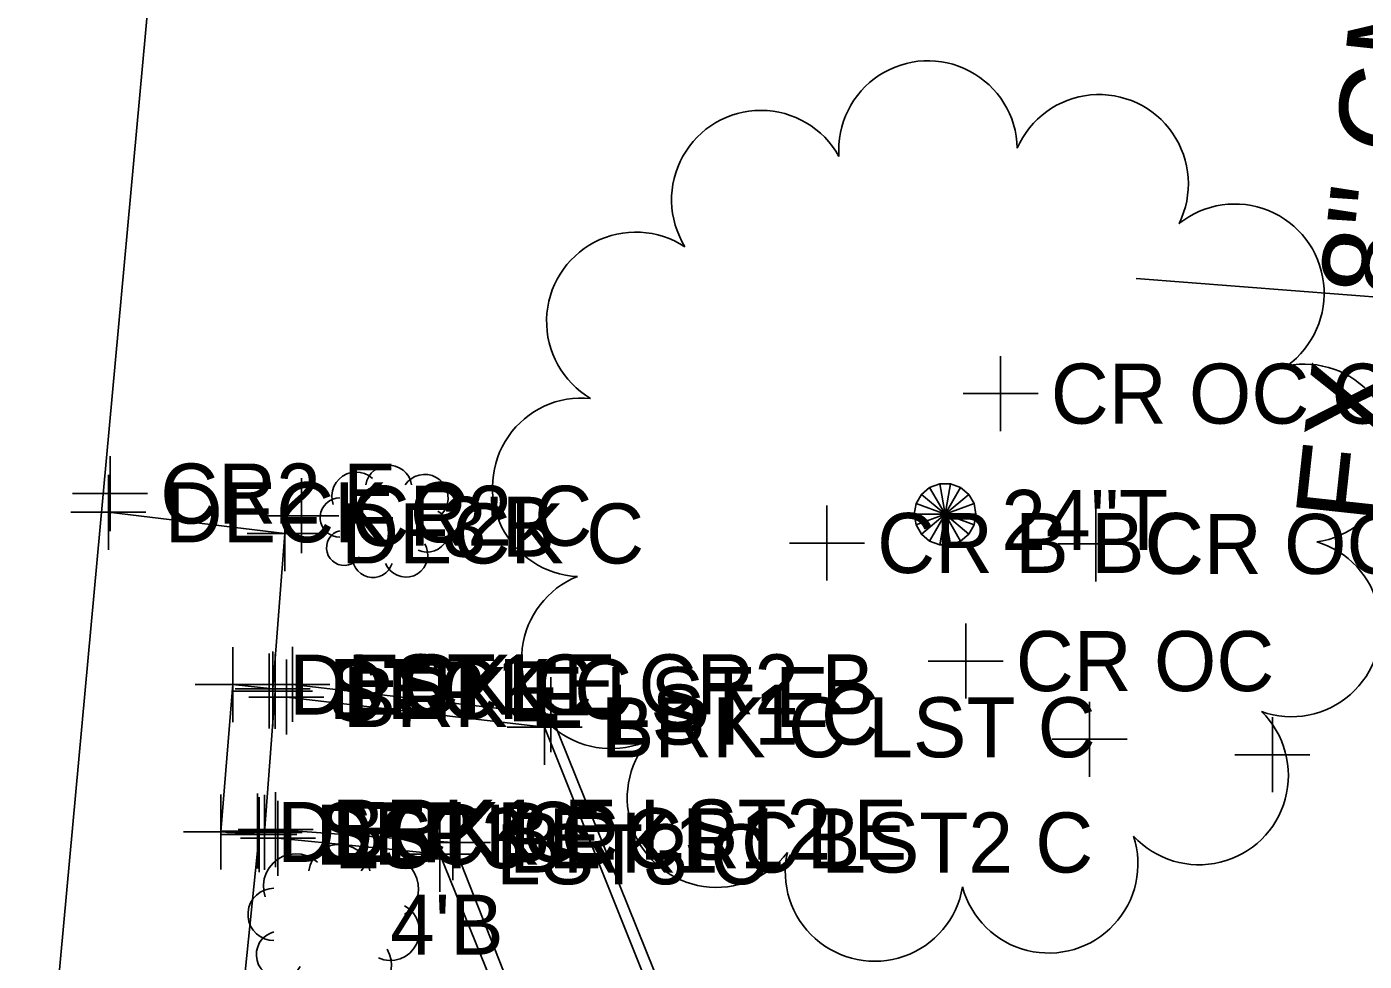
# Model space of a CAD drawing. Extents: x 1363693 to 1365209, y 422201 to 424153.
# Drawn here: x 1364202.37 to 1364238.05, y 423360.62 to 423385.53 of the extents above; entities that cross this region are included whole.
import ezdxf

# ---------------------------------------------------------------- set-up
doc = ezdxf.new("R2010")
doc.units = 0
for name, color, linetype in [('BD_X_Building', 7, 'Continuous'), ('PV_X_Driveway', 7, 'Continuous'), ('RD_X_Misc_Items', 7, 'Continuous'), ('SV_X_Original_Ground', 7, 'Continuous'), ('SV_X_Random_Point', 7, 'Continuous'), ('SV_X_Shot_Marker', 7, 'Continuous'), ('UT_X_Gas_Text', 7, 'Continuous'), ('UT_X_Sanitary_Line', 7, 'Continuous'), ('VG_X_Cells', 7, 'Continuous'), ('VG_X_Flower_Bed', 7, 'Continuous'), ('VG_X_Text', 7, 'Continuous')]:
    doc.layers.add(name, color=color, linetype=linetype)

msp = doc.modelspace()

# ---------------------------------------------------------------- linework, layer by layer
at = {"layer": 'BD_X_Building'}
msp.add_line((1364202.373, 423350.942), (1364205.953, 423389.813), dxfattribs=at)
at = {"layer": 'PV_X_Driveway'}
msp.add_line((1364208.715, 423364.055), (1364208.996, 423367.815), dxfattribs=at)
at = {"layer": 'RD_X_Misc_Items'}
for p, q in [((1364209.254, 423372.021), (1364204.553, 423372.586)), ((1364208.932, 423367.878), (1364209.254, 423372.021)), ((1364207.551, 423364.067), (1364207.868, 423367.994)), ((1364207.868, 423367.994), (1364208.932, 423367.878)), ((1364208.573, 423363.995), (1364207.551, 423364.067)), ((1364208.041, 423358.764), (1364208.573, 423363.995))]:
    msp.add_line(p, q, dxfattribs=at)
at = {"layer": 'SV_X_Original_Ground'}
for p, q in [((1364228.348, 423374.748), (1364228.348, 423376.748)), ((1364227.348, 423375.748), (1364229.348, 423375.748)), ((1364204.597, 423372.085), (1364204.597, 423374.085)), ((1364204.553, 423371.586), (1364204.553, 423373.586)), ((1364209.698, 423371.493), (1364209.698, 423373.493)), ((1364203.597, 423373.085), (1364205.597, 423373.085)), ((1364209.254, 423371.021), (1364209.254, 423373.021)), ((1364203.553, 423372.586), (1364205.553, 423372.586)), ((1364208.698, 423372.493), (1364210.698, 423372.493)), ((1364223.715, 423370.767), (1364223.715, 423372.767)), ((1364230.885, 423370.742), (1364230.885, 423372.742)), ((1364208.254, 423372.021), (1364210.254, 423372.021)), ((1364222.715, 423371.767), (1364224.715, 423371.767)), ((1364229.885, 423371.742), (1364231.885, 423371.742)), ((1364227.415, 423367.619), (1364227.415, 423369.619)), ((1364207.868, 423366.994), (1364207.868, 423368.994)), ((1364208.837, 423366.822), (1364208.837, 423368.822)), ((1364208.932, 423366.878), (1364208.932, 423368.878)), ((1364226.415, 423368.619), (1364228.415, 423368.619)), ((1364206.868, 423367.994), (1364208.868, 423367.994)), ((1364207.932, 423367.878), (1364209.932, 423367.878)), ((1364207.837, 423367.822), (1364209.837, 423367.822)), ((1364230.721, 423365.536), (1364230.721, 423367.536)), ((1364235.594, 423365.123), (1364235.594, 423367.123)), ((1364229.721, 423366.536), (1364231.721, 423366.536)), ((1364234.594, 423366.123), (1364236.594, 423366.123)), ((1364207.551, 423363.067), (1364207.551, 423365.067)), ((1364208.531, 423363.088), (1364208.531, 423365.088)), ((1364208.573, 423362.995), (1364208.573, 423364.995)), ((1364206.551, 423364.067), (1364208.551, 423364.067)), ((1364207.531, 423364.088), (1364209.531, 423364.088)), ((1364207.573, 423363.995), (1364209.573, 423363.995))]:
    msp.add_line(p, q, dxfattribs=at)
at = {"layer": 'SV_X_Random_Point'}
for p, q in [((1364209.459, 423366.999), (1364209.459, 423368.999)), ((1364208.996, 423366.815), (1364208.996, 423368.815)), ((1364208.459, 423367.999), (1364210.459, 423367.999)), ((1364216.348, 423366.193), (1364216.348, 423368.193)), ((1364207.996, 423367.815), (1364209.996, 423367.815)), ((1364215.348, 423367.193), (1364217.348, 423367.193)), ((1364208.715, 423363.055), (1364208.715, 423365.055)), ((1364209.074, 423362.896), (1364209.074, 423364.896)), ((1364213.391, 423362.471), (1364213.391, 423364.471)), ((1364207.715, 423364.055), (1364209.715, 423364.055)), ((1364208.074, 423363.896), (1364210.074, 423363.896)), ((1364212.391, 423363.471), (1364214.391, 423363.471))]:
    msp.add_line(p, q, dxfattribs=at)
at = {"layer": 'SV_X_Shot_Marker'}
for p, q in [((1364209.3, 423366.661), (1364209.3, 423368.661)), ((1364216.183, 423365.855), (1364216.183, 423367.855)), ((1364208.3, 423367.661), (1364210.3, 423367.661)), ((1364215.183, 423366.855), (1364217.183, 423366.855)), ((1364209.009, 423363.129), (1364209.009, 423365.129)), ((1364213.739, 423362.784), (1364213.739, 423364.784)), ((1364208.009, 423364.129), (1364210.009, 423364.129)), ((1364212.739, 423363.784), (1364214.739, 423363.784))]:
    msp.add_line(p, q, dxfattribs=at)
at = {"layer": 'UT_X_Sanitary_Line'}
msp.add_line((1364231.966, 423378.813), (1364264.406, 423376.309), dxfattribs=at)
at = {"layer": 'VG_X_Cells'}
for points in [[(1364211.592, 423373.489), (1364211.494, 423373.563), (1364211.384, 423373.617), (1364211.266, 423373.649), (1364211.144, 423373.658), (1364211.022, 423373.644), (1364210.906, 423373.607), (1364210.798, 423373.549), (1364210.703, 423373.472), (1364210.624, 423373.378), (1364210.564, 423373.271), (1364210.526, 423373.155), (1364210.51, 423373.034), (1364210.517, 423372.911), (1364210.547, 423372.793)], [(1364212.637, 423373.315), (1364212.61, 423373.429), (1364212.561, 423373.536), (1364212.493, 423373.631), (1364212.409, 423373.712), (1364212.31, 423373.775), (1364212.201, 423373.819), (1364212.086, 423373.841), (1364211.969, 423373.841), (1364211.854, 423373.819), (1364211.745, 423373.775), (1364211.647, 423373.712), (1364211.562, 423373.631), (1364211.494, 423373.536), (1364211.446, 423373.429), (1364211.418, 423373.315)], [(1364213.334, 423372.445), (1364213.425, 423372.518), (1364213.5, 423372.607), (1364213.558, 423372.708), (1364213.596, 423372.819), (1364213.613, 423372.934), (1364213.608, 423373.051), (1364213.582, 423373.165), (1364213.535, 423373.271), (1364213.469, 423373.368), (1364213.386, 423373.45), (1364213.29, 423373.516), (1364213.183, 423373.563), (1364213.069, 423373.589), (1364212.953, 423373.594), (1364212.837, 423373.577), (1364212.727, 423373.539), (1364212.626, 423373.481), (1364212.537, 423373.406), (1364212.463, 423373.315)], [(1364210.722, 423372.967), (1364210.625, 423372.958), (1364210.533, 423372.932), (1364210.446, 423372.889), (1364210.37, 423372.831), (1364210.305, 423372.759), (1364210.254, 423372.677), (1364210.219, 423372.587), (1364210.201, 423372.493), (1364210.201, 423372.396), (1364210.219, 423372.302), (1364210.254, 423372.212), (1364210.305, 423372.13), (1364210.37, 423372.058), (1364210.446, 423372), (1364210.533, 423371.957), (1364210.625, 423371.931), (1364210.722, 423371.922)], [(1364212.811, 423371.574), (1364212.917, 423371.539), (1364213.027, 423371.524), (1364213.138, 423371.531), (1364213.246, 423371.558), (1364213.346, 423371.606), (1364213.436, 423371.671), (1364213.512, 423371.753), (1364213.571, 423371.847), (1364213.611, 423371.951), (1364213.631, 423372.06), (1364213.629, 423372.171), (1364213.607, 423372.28), (1364213.564, 423372.383), (1364213.503, 423372.476), (1364213.425, 423372.555), (1364213.334, 423372.619)], [(1364210.722, 423372.096), (1364210.635, 423372.064), (1364210.556, 423372.017), (1364210.488, 423371.954), (1364210.434, 423371.88), (1364210.395, 423371.796), (1364210.373, 423371.707), (1364210.369, 423371.614), (1364210.383, 423371.523), (1364210.415, 423371.437), (1364210.463, 423371.358), (1364210.525, 423371.29), (1364210.599, 423371.235), (1364210.683, 423371.196), (1364210.772, 423371.174), (1364210.864, 423371.17), (1364210.956, 423371.184), (1364211.042, 423371.215), (1364211.121, 423371.263), (1364211.189, 423371.325), (1364211.244, 423371.4)], [(1364211.941, 423371.225), (1364211.993, 423371.124), (1364212.064, 423371.035), (1364212.151, 423370.961), (1364212.25, 423370.906), (1364212.358, 423370.871), (1364212.472, 423370.857), (1364212.585, 423370.866), (1364212.695, 423370.896), (1364212.797, 423370.947), (1364212.887, 423371.016), (1364212.962, 423371.102), (1364213.019, 423371.201), (1364213.055, 423371.309), (1364213.071, 423371.421), (1364213.064, 423371.535), (1364213.035, 423371.645), (1364212.986, 423371.748)], [(1364211.07, 423371.4), (1364211.076, 423371.297), (1364211.101, 423371.197), (1364211.145, 423371.104), (1364211.206, 423371.022), (1364211.281, 423370.952), (1364211.369, 423370.898), (1364211.465, 423370.862), (1364211.567, 423370.845), (1364211.669, 423370.848), (1364211.77, 423370.871), (1364211.864, 423370.912), (1364211.948, 423370.97), (1364212.02, 423371.044), (1364212.076, 423371.13), (1364212.115, 423371.225)], [(1364211.522, 423363.029), (1364211.485, 423363.181), (1364211.42, 423363.323), (1364211.33, 423363.45), (1364211.217, 423363.558), (1364211.085, 423363.643), (1364210.94, 423363.701), (1364210.787, 423363.73), (1364210.631, 423363.73), (1364210.477, 423363.701), (1364210.333, 423363.643), (1364210.201, 423363.558), (1364210.088, 423363.45), (1364209.998, 423363.323), (1364209.933, 423363.181), (1364209.896, 423363.029)], [(1364210.128, 423363.261), (1364209.998, 423363.359), (1364209.851, 423363.431), (1364209.694, 423363.473), (1364209.531, 423363.486), (1364209.369, 423363.467), (1364209.213, 423363.418), (1364209.069, 423363.341), (1364208.943, 423363.238), (1364208.838, 423363.113), (1364208.758, 423362.97), (1364208.707, 423362.815), (1364208.685, 423362.654), (1364208.695, 423362.491), (1364208.735, 423362.332)], [(1364212.451, 423361.868), (1364212.571, 423361.966), (1364212.672, 423362.085), (1364212.749, 423362.22), (1364212.8, 423362.367), (1364212.822, 423362.521), (1364212.816, 423362.676), (1364212.781, 423362.828), (1364212.718, 423362.971), (1364212.631, 423363.099), (1364212.521, 423363.209), (1364212.392, 423363.297), (1364212.25, 423363.359), (1364212.098, 423363.394), (1364211.942, 423363.401), (1364211.788, 423363.378), (1364211.641, 423363.328), (1364211.506, 423363.251), (1364211.387, 423363.15), (1364211.289, 423363.029)], [(1364208.967, 423362.565), (1364208.839, 423362.553), (1364208.716, 423362.518), (1364208.601, 423362.46), (1364208.498, 423362.383), (1364208.411, 423362.288), (1364208.344, 423362.179), (1364208.297, 423362.059), (1364208.274, 423361.932), (1364208.274, 423361.804), (1364208.297, 423361.677), (1364208.344, 423361.557), (1364208.411, 423361.448), (1364208.498, 423361.353), (1364208.601, 423361.276), (1364208.716, 423361.218), (1364208.839, 423361.183), (1364208.967, 423361.171)], [(1364211.754, 423360.707), (1364211.895, 423360.66), (1364212.042, 423360.641), (1364212.19, 423360.65), (1364212.333, 423360.687), (1364212.467, 423360.75), (1364212.587, 423360.837), (1364212.688, 423360.946), (1364212.766, 423361.071), (1364212.82, 423361.21), (1364212.846, 423361.356), (1364212.844, 423361.504), (1364212.814, 423361.649), (1364212.758, 423361.786), (1364212.676, 423361.91), (1364212.572, 423362.016), (1364212.451, 423362.1)], [(1364208.967, 423361.404), (1364208.852, 423361.361), (1364208.747, 423361.297), (1364208.656, 423361.214), (1364208.584, 423361.115), (1364208.532, 423361.003), (1364208.503, 423360.884), (1364208.498, 423360.761), (1364208.516, 423360.64), (1364208.558, 423360.524), (1364208.622, 423360.419), (1364208.705, 423360.328), (1364208.804, 423360.256), (1364208.916, 423360.204), (1364209.035, 423360.174), (1364209.158, 423360.169), (1364209.279, 423360.187), (1364209.395, 423360.229), (1364209.5, 423360.293), (1364209.591, 423360.376), (1364209.664, 423360.475)], [(1364210.593, 423360.243), (1364210.663, 423360.108), (1364210.757, 423359.989), (1364210.873, 423359.891), (1364211.006, 423359.817), (1364211.15, 423359.77), (1364211.301, 423359.751), (1364211.452, 423359.763), (1364211.598, 423359.803), (1364211.734, 423359.871), (1364211.854, 423359.964), (1364211.954, 423360.078), (1364212.03, 423360.21), (1364212.079, 423360.353), (1364212.1, 423360.504), (1364212.09, 423360.655), (1364212.052, 423360.802), (1364211.986, 423360.939)]]:
    msp.add_lwpolyline(points, dxfattribs=at)
for points in [[(1364226.453, 423373.248), (1364226.865, 423372.534), (1364226.865, 423372.534), (1364226.234, 423373.064)], [(1364226.722, 423373.346), (1364226.865, 423372.534), (1364226.865, 423372.534), (1364226.453, 423373.248)], [(1364227.008, 423373.346), (1364226.865, 423372.534), (1364226.865, 423372.534), (1364226.722, 423373.346)], [(1364227.277, 423373.248), (1364226.865, 423372.534), (1364226.865, 423372.534), (1364227.008, 423373.346)], [(1364227.496, 423373.064), (1364226.865, 423372.534), (1364226.865, 423372.534), (1364227.277, 423373.248)], [(1364226.234, 423373.064), (1364226.865, 423372.534), (1364226.865, 423372.534), (1364226.091, 423372.816)], [(1364227.639, 423372.816), (1364226.865, 423372.534), (1364226.865, 423372.534), (1364227.496, 423373.064)], [(1364226.091, 423372.816), (1364226.865, 423372.534), (1364226.865, 423372.534), (1364226.041, 423372.534)], [(1364226.041, 423372.534), (1364226.865, 423372.534), (1364226.865, 423372.534), (1364226.091, 423372.252)], [(1364226.091, 423372.252), (1364226.865, 423372.534), (1364226.865, 423372.534), (1364226.234, 423372.004)], [(1364226.234, 423372.004), (1364226.865, 423372.534), (1364226.865, 423372.534), (1364226.453, 423371.82)], [(1364226.453, 423371.82), (1364226.865, 423372.534), (1364226.865, 423372.534), (1364226.722, 423371.722)], [(1364226.722, 423371.722), (1364226.865, 423372.534), (1364226.865, 423372.534), (1364227.008, 423371.722)], [(1364227.689, 423372.534), (1364226.865, 423372.534), (1364226.865, 423372.534), (1364227.639, 423372.816)], [(1364227.008, 423371.722), (1364226.865, 423372.534), (1364226.865, 423372.534), (1364227.277, 423371.82)], [(1364227.277, 423371.82), (1364226.865, 423372.534), (1364226.865, 423372.534), (1364227.496, 423372.004)], [(1364227.496, 423372.004), (1364226.865, 423372.534), (1364226.865, 423372.534), (1364227.639, 423372.252)], [(1364227.639, 423372.252), (1364226.865, 423372.534), (1364226.865, 423372.534), (1364227.689, 423372.534)]]:
    msp.add_lwpolyline(points, close=True, dxfattribs=at)
for centre, start, end in [((1364226.41, 423382.24), 1.241, 184.1237), ((1364230.973, 423381.339), 333.5487, 156.4314), ((1364221.952, 423380.917), 28.9333, 211.816), ((1364234.594, 423378.422), 305.8564, 128.7391), ((1364218.619, 423377.673), 56.6256, 239.5083), ((1364236.445, 423374.155), 278.1641, 101.0468), ((1364217.175, 423373.252), 84.3179, 267.2006), ((1364236.101, 423369.517), 250.4718, 73.3545), ((1364217.951, 423368.667), 112.0103, 294.8929), ((1364233.641, 423365.571), 222.7795, 45.6622), ((1364220.769, 423364.968), 139.7026, 322.5852), ((1364229.629, 423363.219), 195.0872, 17.9699), ((1364224.984, 423363.001), 167.3949, 350.2776)]:
    msp.add_arc(centre, 2.381, start, end, dxfattribs=at)
at = {"layer": 'VG_X_Flower_Bed'}
for p, q in [((1364216.348, 423367.193), (1364209.459, 423367.999)), ((1364216.183, 423366.855), (1364209.3, 423367.661)), ((1364220.342, 423357.324), (1364216.348, 423367.193)), ((1364219.968, 423357.395), (1364216.183, 423366.855)), ((1364213.739, 423363.784), (1364209.009, 423364.129)), ((1364213.391, 423363.471), (1364209.074, 423363.896)), ((1364218.887, 423350.681), (1364213.739, 423363.784)), ((1364218.504, 423350.846), (1364213.391, 423363.471))]:
    msp.add_line(p, q, dxfattribs=at)

# ---------------------------------------------------------------- texts
at = {"layer": 'SV_X_Original_Ground'}
for s, p in [('CR OC CLS', (1364229.685, 423374.948)), ('CR2 E', (1364205.934, 423372.285)), ('DECK C', (1364206.053, 423371.786)), ('CR2 C', (1364211.035, 423371.693)), ('DECK C', (1364210.754, 423371.221)), ('CR B BC', (1364225.052, 423370.967)), ('CR OC', (1364232.222, 423370.942)), ('CR OC', (1364228.752, 423367.819)), ('DECK C', (1364209.368, 423367.194)), ('DECK C', (1364210.432, 423367.078)), ('DECK C', (1364209.051, 423363.267)), ('DECK C', (1364210.073, 423363.195))]:
    msp.add_text(s, height=1.6, dxfattribs=at).set_placement(p)
at = {"layer": 'SV_X_Random_Point'}
for s, p in [('STP E', (1364210.435, 423367.015)), ('LST1 E CR2 B', (1364210.959, 423367.199)), ('LST1 C', (1364217.848, 423366.393)), ('STP B', (1364210.154, 423363.255)), ('LST3 E CR1 B', (1364210.574, 423363.096)), ('LST3 C', (1364214.891, 423362.671))]:
    msp.add_text(s, height=1.6, dxfattribs=at).set_placement(p)
at = {"layer": 'SV_X_Shot_Marker'}
for s, p in [('BRK E LST E', (1364210.8, 423366.861)), ('BRK C LST C', (1364217.683, 423366.055)), ('BRK1 E LST2 E', (1364210.509, 423363.329)), ('BRK1 C LST2 C', (1364215.239, 423362.984))]:
    msp.add_text(s, height=1.6, dxfattribs=at).set_placement(p)
at = {"layer": 'UT_X_Gas_Text'}
msp.add_text('EX. 8" GM', height=2.4, rotation=83.8091, dxfattribs=at).set_placement((1364238.588, 423372.199))
at = {"layer": 'VG_X_Text'}
for s, p in [('24"T', (1364228.365, 423371.582)), ("3'B", (1364213.445, 423371.401)), ("4'B", (1364212.065, 423360.794))]:
    msp.add_text(s, height=1.6, dxfattribs=at).set_placement(p)

doc.saveas('drawing.dxf')
